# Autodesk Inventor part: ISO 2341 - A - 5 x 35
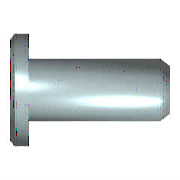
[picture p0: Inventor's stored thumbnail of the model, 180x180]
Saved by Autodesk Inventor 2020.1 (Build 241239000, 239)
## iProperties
Created: 2019-01
Part Number: ISO 2341 - A - 5 x 35
Material: Steel, Mild
Description: Clevis pin
Document SubType Name: Modeling
Standard: ISO 2341
Designer: Safarabadi
Standards Organization: DIN
Language: en-US
Size Designation: A - 5 x 35
Categories: <MemberInstance><Categories><Category DisplayName="Fasteners" InternalName="e4da775c-781d-43d5-af7c-5136215cf5a6" Mnemonic="FSTN"><Category DisplayName="Pins" I
Density: 7.85 g/cm^3
Appearance: Semi-Polished
IsCustomPart: 1
Author: Safarabadi
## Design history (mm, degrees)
sketch "Sketch1"
  geometry: L1 (-1.6, 0)-(-1.6, 4); L2 (-1.6, 4)-(0, 4); L3 (0, 4)-(0, 2.5); L4 (0, 2.5)-(35, 2.5); L5 (35, 2.5)-(35, 0); L6 (-1.6, 0)-(35, 0); L7 (-4, 0)-(17, 0) reference; L8 (0, -0.5)-(0, 3) reference
  constraints: 12 end point, 3 parallel, 2 collinear, 2 perpendicular, 1 vertical
  dimensions: "d0" = 1.6 distance of L1.end L2.end (= KOH); "d1" = 35 distance of L3.end L4.end (= NLG); "d2" = 5 diameter of L4 L6 (= NND); "d3" = 8 diameter of L2 L6 (= KOD)
revolve "Body" sketch "Sketch1" stored, may be unused: angle "d5" = 90 deg
sketch "Sketch2"
  geometry: L1 (0, 0)-(17, 0); 2 further points
  constraints: 2 coincident, 2 end point, 1 horizontal
  dimensions: "d15" = 17 distance of L1.start L1.end
hole "Hole1" sketch "Sketch2" at (17, 0) diameter "d16" = 2; stored, may be unused: countersink angle "d20" = 90 deg, drill point angle "d22" = 118 deg; dims "d17" = 6, "d18" = 4, "d19" = 2, "d21" = 8
body "Solid1"
chamfer "Chamfer1" distance "d7" = 2 (= PHH1); stored, may be unused: angle "d8" = 30 deg (= FAWI1), second distance "d12" = 2 (= PHH1)
chamfer "Chamfer2" distance "d4" = 1 (= PHH2); stored, may be unused: angle "d6" = 45 deg (= FAWI2), second distance "d13" = 1 (= PHH2)
other parameters: "NLG" = 35 [user parameter; used in 1 equation term], "KOH" = 1.6 [user parameter; used in 1 equation term], "KOD" = 8 [user parameter; used in 1 equation term], "NND" = 5 [user parameter; used in 1 equation term], "FAWI1" = 30 deg [user parameter; used in 1 equation term], "FAWI2" = 45 deg [user parameter; used in 1 equation term], "PHH2" = 1 [user parameter; used in 2 equation terms], "PHH1" = 2 [user parameter; used in 2 equation terms], "d9" = 0, "d10" = 0, "d14" = 0
